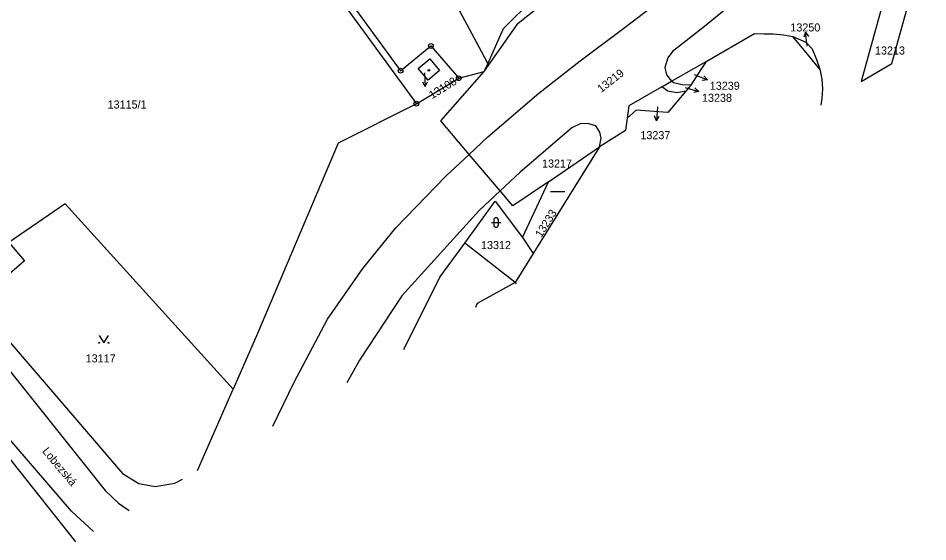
# Model space of a CAD drawing. Extents: x -821458 to -820266, y -1071458 to -1069826.
# Drawn here: x -820498 to -820306.2, y -1071372.4 to -1071261.9 of the extents above; entities that cross this region are included whole.
import ezdxf

# ---------------------------------------------------------------- set-up
doc = ezdxf.new("R2010")
doc.units = 0
for name, color, linetype in [('Vrstva 1', 7, 'Continuous'), ('Vrstva 13', 7, 'Continuous'), ('Vrstva 2', 7, 'Continuous'), ('Vrstva 3', 7, 'Continuous'), ('Vrstva 4', 7, 'Continuous'), ('Vrstva 5', 7, 'Continuous'), ('Vrstva 7', 7, 'Continuous'), ('Vrstva 8', 7, 'Continuous')]:
    doc.layers.add(name, color=color, linetype=linetype)

msp = doc.modelspace()

# ---------------------------------------------------------------- linework, layer by layer
at = {"layer": 'Vrstva 1'}
for p, q in [((-820458.31, -1071219.13), (-820414.04, -1071279.95)), ((-820331.51, -1071269.54), (-820334.6, -1071265.8)), ((-820328.9, -1071272.7), (-820331.51, -1071269.54)), ((-820399.7, -1071273.16), (-820398.96, -1071271.52)), ((-820360.23, -1071275.23), (-820352.9, -1071271.02)), ((-820329.6, -1071270.6), (-820328.9, -1071272.7)), ((-820405.1, -1071274.59), (-820399.7, -1071273.16)), ((-820328.9, -1071272.7), (-820328.53, -1071274.8)), ((-820414.04, -1071279.95), (-820405.1, -1071274.59)), ((-820362.27, -1071276.4), (-820360.23, -1071275.23)), ((-820356.15, -1071276.05), (-820357.21, -1071277.31)), ((-820396.37, -1071298.36), (-820402.91, -1071290.65)), ((-820375.37, -1071289.06), (-820389.38, -1071311.54)), ((-820386.15, -1071296.47), (-820375.37, -1071289.06)), ((-820391.62, -1071308.2), (-820386.15, -1071296.47)), ((-820393.2, -1071317.68), (-820403.82, -1071309.37)), ((-820391.62, -1071308.2), (-820389.38, -1071311.54)), ((-820389.38, -1071311.54), (-820393.2, -1071317.68))]:
    msp.add_line(p, q, dxfattribs=at)
for points in [[(-820425.02, -1071222.9), (-820431.56, -1071232.21), (-820433.1, -1071251.37), (-820417.36, -1071272.99), (-820410.98, -1071267.78), (-820405.1, -1071274.59)], [(-820425.02, -1071222.9), (-820400.38, -1071268.87), (-820398.96, -1071271.52)], [(-820399.7, -1071273.16), (-820392.58, -1071262.99), (-820375.9, -1071249.7), (-820374.1, -1071251.5), (-820351.38, -1071237.19), (-820356.32, -1071229.9)], [(-820402.91, -1071290.65), (-820398.95, -1071286.93), (-820388.19, -1071277.72), (-820379.51, -1071270.89), (-820370.53, -1071264.24), (-820358.49, -1071254.97), (-820348.34, -1071246.63), (-820345.74, -1071242.13), (-820347.25, -1071236.15)], [(-820326.72, -1071239.67), (-820331.97, -1071245.01), (-820342.31, -1071254.65), (-820353.61, -1071263.96), (-820360.02, -1071268.97), (-820360.98, -1071270.3), (-820361.65, -1071272.32), (-820361.24, -1071273.9), (-820360.23, -1071275.23)], [(-820398.96, -1071271.52), (-820395.64, -1071264.1), (-820382.79, -1071251.27)], [(-820352.9, -1071271.02), (-820342.71, -1071265.17), (-820340.7, -1071265.2), (-820338.8, -1071265.2), (-820336.6, -1071265.4), (-820334.6, -1071265.8)], [(-820334.6, -1071265.8), (-820331.9, -1071267), (-820330.56, -1071268.37), (-820329.6, -1071270.6)], [(-820409.14, -1071272.96), (-820411.57, -1071275.02), (-820413.69, -1071272.51), (-820411.19, -1071270.46), (-820409.14, -1071272.96)], [(-820352.9, -1071271.02), (-820354.02, -1071272.75), (-820356.15, -1071276.05)], [(-820402.91, -1071290.65), (-820408.9, -1071283.6), (-820399.7, -1071273.16)], [(-820356.15, -1071276.05), (-820357.97, -1071276.01), (-820359.78, -1071275.55), (-820360.23, -1071275.23)], [(-820328.53, -1071274.8), (-820328.36, -1071276.81), (-820328.49, -1071278.81), (-820328.72, -1071280.27)], [(-820362.27, -1071276.4), (-820369.2, -1071280.4), (-820369.55, -1071283.01)], [(-820357.21, -1071277.31), (-820361, -1071281.8), (-820367.7, -1071281.3), (-820369.55, -1071283.01)], [(-820357.21, -1071277.31), (-820359.07, -1071277.68), (-820360.98, -1071277.28), (-820362.27, -1071276.4)], [(-820414.04, -1071279.95), (-820430.54, -1071288.3), (-820447.55, -1071328.41), (-820452.69, -1071340.19)], [(-820485.86, -1071372.38), (-820533.17, -1071312.78), (-820547.67, -1071295.15), (-820551.62, -1071291.15), (-820556.95, -1071290.24), (-820564.58, -1071281.57)], [(-820369.55, -1071283.01), (-820369.9, -1071285.6), (-820375.37, -1071289.06)], [(-820375.37, -1071289.06), (-820375.05, -1071287.25), (-820375.3, -1071285.97), (-820376.15, -1071284.61), (-820377.97, -1071284.14), (-820379.5, -1071284.2), (-820381.22, -1071285.02), (-820392.22, -1071294.47), (-820396.37, -1071298.36)], [(-820386.15, -1071296.47), (-820393.7, -1071301.5), (-820396.37, -1071298.36)], [(-820452.69, -1071340.19), (-820488.09, -1071301.05), (-820500.02, -1071309.25)], [(-820403.82, -1071309.37), (-820397.4, -1071300.53), (-820391.62, -1071308.2)], [(-820500.02, -1071309.25), (-820496.69, -1071313.12), (-820506.98, -1071321.94)], [(-820416.67, -1071331.82), (-820409.06, -1071316.57), (-820403.82, -1071309.37)], [(-820393.2, -1071317.68), (-820401.18, -1071322.13), (-820401.55, -1071322.96)], [(-820393.2, -1071317.68), (-820392.99, -1071317.94)], [(-820506.98, -1071321.94), (-820506.97, -1071321.95), (-820476, -1071357.98), (-820472.55, -1071360.07), (-820469.1, -1071360.69), (-820464.99, -1071360.03), (-820463.37, -1071359.2)], [(-820460.18, -1071357.33), (-820452.69, -1071340.19)]]:
    msp.add_lwpolyline(points, dxfattribs=at)
at = {"layer": 'Vrstva 13'}
msp.add_line((-820320.21, -1071275.28), (-820313.77, -1071271.5), dxfattribs=at)
msp.add_lwpolyline([(-820313.77, -1071271.5), (-820306.15, -1071244.05), (-820311.18, -1071242.67), (-820320.21, -1071275.28)], dxfattribs=at)
at = {"layer": 'Vrstva 3'}
for p, q in [((-820385.71, -1071298.49), (-820382.71, -1071298.49)), ((-820398.21, -1071305.01), (-820396.21, -1071305.01)), ((-820397.71, -1071304.51), (-820397.71, -1071305.51)), ((-820396.71, -1071305.51), (-820396.71, -1071304.51))]:
    msp.add_line(p, q, dxfattribs=at)
msp.add_lwpolyline([(-820480.97, -1071328.89), (-820479.97, -1071330.39), (-820478.97, -1071328.89)], dxfattribs=at)
for centre in [(-820480.97, -1071330.39), (-820478.97, -1071330.39)]:
    msp.add_circle(centre, 0.1, dxfattribs=at)
for centre, start, end in [((-820397.21, -1071304.51), 0, 180), ((-820397.21, -1071305.51), 180, 359.9879)]:
    msp.add_arc(centre, 0.5, start, end, dxfattribs=at)
at = {"layer": 'Vrstva 4'}
for p, q in [((-820540.54, -1071285.54), (-820479.66, -1071361.53)), ((-820407.82, -1071295.25), (-820402.91, -1071290.65)), ((-820486.8, -1071365.91), (-820547.67, -1071295.15)), ((-820418.38, -1071306.16), (-820407.82, -1071295.25)), ((-820396.37, -1071298.36), (-820400.81, -1071302.52)), ((-820400.81, -1071302.52), (-820417.11, -1071320.5)), ((-820425.36, -1071314.69), (-820418.38, -1071306.16)), ((-820432.75, -1071325.44), (-820425.36, -1071314.69)), ((-820417.11, -1071320.5), (-820426.04, -1071334.07)), ((-820439.84, -1071338.72), (-820432.75, -1071325.44)), ((-820426.04, -1071334.07), (-820428.67, -1071338.86)), ((-820444.29, -1071348.01), (-820439.84, -1071338.72)), ((-820479.66, -1071361.53), (-820476.86, -1071364.24)), ((-820476.86, -1071364.24), (-820474.61, -1071365.79)), ((-820482.14, -1071370.2), (-820486.8, -1071365.91))]:
    msp.add_line(p, q, dxfattribs=at)
at = {"layer": 'Vrstva 5'}
msp.add_circle((-820411.4, -1071272.92), 0.175, dxfattribs=at)
at = {"layer": 'Vrstva 7'}
for p, q in [((-820331.93, -1071264.86), (-820332.33, -1071265.91)), ((-820331.62, -1071267.85), (-820331.93, -1071264.86)), ((-820331.93, -1071264.86), (-820331.33, -1071265.81)), ((-820412.3, -1071273.44), (-820412.15, -1071276.32)), ((-820412.15, -1071276.32), (-820412.68, -1071275.38)), ((-820412.15, -1071276.32), (-820411.72, -1071275.33)), ((-820355.42, -1071273.83), (-820352.64, -1071274.95)), ((-820352.64, -1071274.95), (-820353.75, -1071275.04)), ((-820352.64, -1071274.95), (-820353.38, -1071274.11)), ((-820357.32, -1071276.54), (-820354.44, -1071277.37)), ((-820354.44, -1071277.37), (-820355.54, -1071277.57)), ((-820354.44, -1071277.37), (-820355.26, -1071276.61)), ((-820363.18, -1071280.59), (-820363.39, -1071283.58)), ((-820363.39, -1071283.58), (-820363.82, -1071282.55)), ((-820363.39, -1071283.58), (-820362.82, -1071282.62))]:
    msp.add_line(p, q, dxfattribs=at)
at = {"layer": 'Vrstva 8'}
for centre, radius in [((-820410.98, -1071267.78), 0.5), ((-820410.98, -1071267.78), 0.0303), ((-820417.36, -1071272.99), 0.5), ((-820417.36, -1071272.99), 0.0303), ((-820405.1, -1071274.59), 0.5), ((-820405.1, -1071274.59), 0.0303), ((-820414.04, -1071279.95), 0.5), ((-820414.04, -1071279.95), 0.0303)]:
    msp.add_circle(centre, radius, dxfattribs=at)

# ---------------------------------------------------------------- texts
at = {"layer": 'Vrstva 2'}
for s, p in [('13250', (-820335.15, -1071264.72)), ('13213', (-820317.29, -1071269.58)), ('13239', (-820352.14, -1071277.02)), ('13115/1', (-820479.17, -1071280.97)), ('13238', (-820353.78, -1071279.56)), ('13237', (-820366.78, -1071287.44)), ('13217', (-820387.53, -1071293.43)), ('13312', (-820400.4, -1071310.63)), ('13117', (-820483.8, -1071334.54))]:
    msp.add_text(s, height=1.7, dxfattribs=at).set_placement(p)
for s, rotation, p in [('13219', 38, (-820375.04, -1071277.72)), ('13108', 32, (-820410.72, -1071279.02)), ('13233', 58, (-820387.67, -1071308.32))]:
    msp.add_text(s, height=1.7, rotation=rotation, dxfattribs=at).set_placement(p)
at = {"layer": 'Vrstva 7'}
msp.add_text('Lobezská', height=1.7, rotation=310, dxfattribs=at).set_placement((-820493.06, -1071353.33))

doc.saveas('drawing.dxf')
